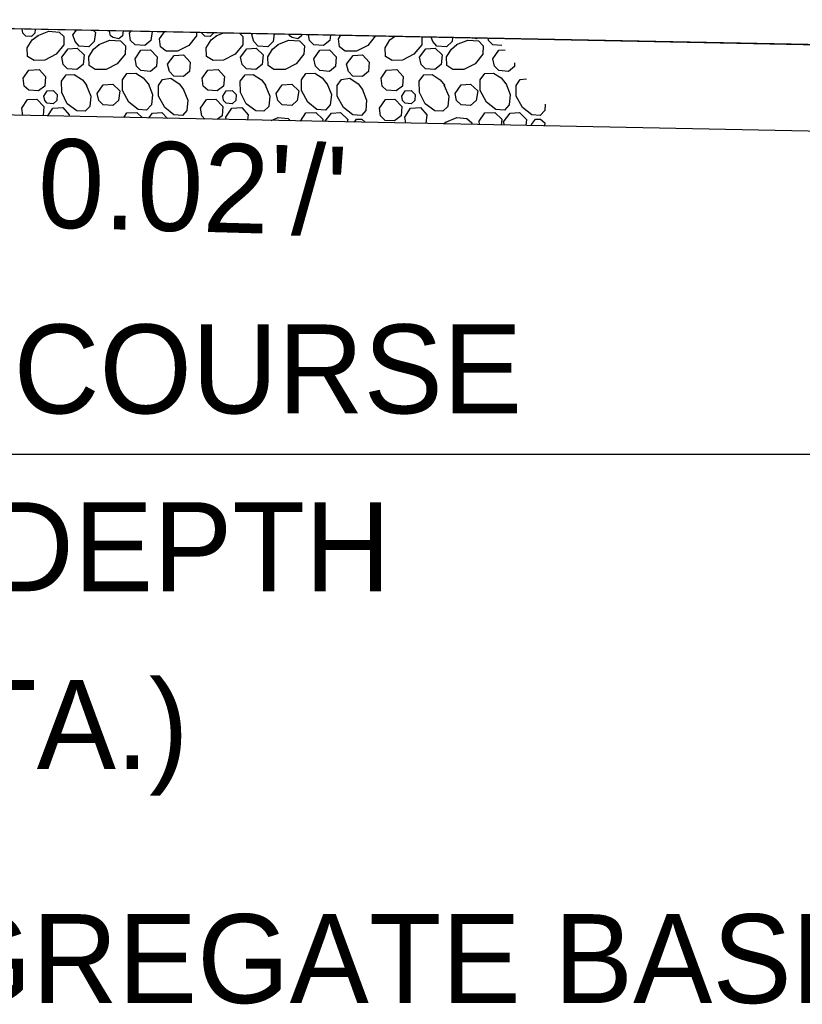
# Model space of a CAD drawing. Extents: x 2478 to 3210, y 439 to 841.
# Drawn here: x 2631.89 to 2642.46, y 475.8 to 489.09 of the extents above; entities that cross this region are included whole.
import ezdxf

# ---------------------------------------------------------------- set-up
doc = ezdxf.new("R2010")
doc.units = 0
for name, color, linetype in [('19', 7, 'Continuous'), ('R_Annotation', 7, 'Continuous'), ('R_Dimension', 7, 'Continuous')]:
    doc.layers.add(name, color=color, linetype=linetype)

msp = doc.modelspace()

# ---------------------------------------------------------------- linework, layer by layer
at = {"layer": '19'}
msp.add_lwpolyline([(2604.697, 489.114), (2604.445, 488.609), (2627.034, 489.061), (2649.623, 488.609), (2649.371, 489.114), (2627.034, 489.561)], close=True, dxfattribs=at)
at = {"layer": 'R_Annotation'}
for p, q in [((2649.623, 488.609), (2627.034, 489.061)), ((2666.487, 487.104), (2627.034, 487.893))]:
    msp.add_line(p, q, dxfattribs=at)
at = {"layer": 'R_Dimension'}
for p, q in [((2632.609, 488.881), (2632.658, 488.948)), ((2633.104, 488.931), (2633.11, 488.939)), ((2633.374, 488.906), (2633.391, 488.933)), ((2634.544, 488.871), (2634.642, 488.908)), ((2635.024, 488.881), (2635.038, 488.9)), ((2631.933, 487.795), (2631.919, 487.891)), ((2634.68, 487.74), (2634.674, 487.771)), ((2637.105, 487.692), (2637.089, 487.771)), ((2637.611, 487.682), (2637.649, 487.711)), ((2638.1, 487.672), (2638.094, 487.716)), ((2638.438, 487.665), (2638.424, 487.711)), ((2638.801, 487.658), (2638.799, 487.671)), ((2649.034, 483.219), (2605.034, 483.219))]:
    msp.add_line(p, q, dxfattribs=at)
for points in [[(2632.101, 488.959), (2632.094, 488.906), (2632.049, 488.861), (2631.974, 488.866), (2631.934, 488.906), (2631.924, 488.963)], [(2632.129, 488.871), (2632.284, 488.931), (2632.424, 488.921), (2632.489, 488.861), (2632.489, 488.746), (2632.384, 488.621), (2632.229, 488.541), (2632.089, 488.536), (2631.999, 488.591), (2631.994, 488.706), (2632.059, 488.816), (2632.139, 488.876)], [(2632.888, 488.943), (2632.914, 488.916), (2632.899, 488.791), (2632.824, 488.721), (2632.694, 488.731), (2632.639, 488.791), (2632.609, 488.881)], [(2633.287, 488.935), (2633.279, 488.871), (2633.229, 488.831), (2633.154, 488.846), (2633.119, 488.871), (2633.104, 488.931)], [(2633.679, 488.928), (2633.664, 488.806), (2633.579, 488.741), (2633.449, 488.746), (2633.389, 488.806), (2633.374, 488.906)], [(2634.279, 488.916), (2634.279, 488.871), (2634.174, 488.741), (2634.024, 488.661), (2633.869, 488.661), (2633.794, 488.721), (2633.779, 488.831), (2633.846, 488.924)], [(2634.51, 488.911), (2634.509, 488.906), (2634.464, 488.861), (2634.389, 488.866), (2634.349, 488.906), (2634.348, 488.914)], [(2634.857, 488.904), (2634.904, 488.861), (2634.904, 488.746), (2634.799, 488.621), (2634.644, 488.541), (2634.504, 488.536), (2634.414, 488.591), (2634.409, 488.706), (2634.474, 488.816), (2634.554, 488.876)], [(2635.326, 488.895), (2635.314, 488.791), (2635.239, 488.721), (2635.109, 488.731), (2635.054, 488.791), (2635.024, 488.881)], [(2635.696, 488.887), (2635.694, 488.871), (2635.644, 488.831), (2635.569, 488.846), (2635.534, 488.871), (2635.529, 488.891)], [(2636.088, 488.879), (2636.079, 488.806), (2635.994, 488.741), (2635.864, 488.746), (2635.804, 488.806), (2635.792, 488.885)], [(2636.691, 488.867), (2636.589, 488.741), (2636.439, 488.661), (2636.284, 488.661), (2636.209, 488.721), (2636.194, 488.831), (2636.227, 488.877)], [(2636.882, 488.864), (2636.879, 488.861), (2636.813, 488.865)], [(2637.319, 488.855), (2637.319, 488.746), (2637.214, 488.621), (2637.059, 488.541), (2636.919, 488.536), (2636.829, 488.591), (2636.824, 488.706), (2636.889, 488.816), (2636.951, 488.862)], [(2632.959, 488.751), (2633.109, 488.811), (2633.254, 488.801), (2633.319, 488.736), (2633.314, 488.621), (2633.209, 488.491), (2633.059, 488.416), (2632.909, 488.416), (2632.829, 488.471), (2632.824, 488.586), (2632.889, 488.691), (2632.964, 488.751)], [(2635.374, 488.751), (2635.524, 488.811), (2635.669, 488.801), (2635.734, 488.736), (2635.729, 488.621), (2635.624, 488.491), (2635.474, 488.416), (2635.324, 488.416), (2635.244, 488.471), (2635.239, 488.586), (2635.304, 488.691), (2635.379, 488.751)], [(2637.736, 488.846), (2637.729, 488.791), (2637.654, 488.721), (2637.524, 488.731), (2637.469, 488.791), (2637.448, 488.852)], [(2637.789, 488.751), (2637.939, 488.811), (2638.084, 488.801), (2638.149, 488.736), (2638.144, 488.621), (2638.039, 488.491), (2637.889, 488.416), (2637.739, 488.416), (2637.659, 488.471), (2637.654, 488.586), (2637.719, 488.691), (2637.794, 488.751)], [(2638.071, 488.84), (2638.059, 488.831), (2638.006, 488.841)], [(2638.398, 488.741), (2638.279, 488.746), (2638.219, 488.806), (2638.214, 488.837)], [(2632.459, 488.581), (2632.544, 488.696), (2632.669, 488.701), (2632.764, 488.611), (2632.749, 488.481), (2632.664, 488.416), (2632.539, 488.426), (2632.479, 488.481), (2632.459, 488.581)], [(2633.449, 488.561), (2633.529, 488.676), (2633.659, 488.681), (2633.749, 488.586), (2633.739, 488.456), (2633.659, 488.386), (2633.529, 488.401), (2633.469, 488.461), (2633.449, 488.561)], [(2633.889, 488.486), (2633.979, 488.606), (2634.104, 488.611), (2634.194, 488.516), (2634.184, 488.386), (2634.104, 488.321), (2633.974, 488.326), (2633.914, 488.386), (2633.889, 488.486)], [(2634.874, 488.581), (2634.959, 488.696), (2635.084, 488.701), (2635.179, 488.611), (2635.164, 488.481), (2635.079, 488.416), (2634.954, 488.426), (2634.894, 488.481), (2634.874, 488.581)], [(2635.864, 488.561), (2635.944, 488.676), (2636.074, 488.681), (2636.164, 488.586), (2636.154, 488.456), (2636.074, 488.386), (2635.944, 488.401), (2635.884, 488.461), (2635.864, 488.561)], [(2636.304, 488.486), (2636.394, 488.606), (2636.519, 488.611), (2636.609, 488.516), (2636.599, 488.386), (2636.519, 488.321), (2636.389, 488.326), (2636.329, 488.386), (2636.304, 488.486)], [(2637.289, 488.581), (2637.374, 488.696), (2637.499, 488.701), (2637.594, 488.611), (2637.579, 488.481), (2637.494, 488.416), (2637.369, 488.426), (2637.309, 488.481), (2637.289, 488.581)], [(2638.279, 488.561), (2638.359, 488.676), (2638.444, 488.679)], [(2638.573, 488.505), (2638.569, 488.456), (2638.489, 488.386), (2638.359, 488.401), (2638.299, 488.461), (2638.279, 488.561)], [(2631.939, 488.296), (2632.014, 488.406), (2632.154, 488.416), (2632.239, 488.321), (2632.229, 488.191), (2632.144, 488.126), (2632.014, 488.136), (2631.954, 488.191), (2631.939, 488.296)], [(2632.789, 488.206), (2632.854, 488.056), (2632.839, 487.916), (2632.774, 487.851), (2632.664, 487.856), (2632.534, 487.951), (2632.459, 488.106), (2632.454, 488.256), (2632.519, 488.341), (2632.629, 488.346), (2632.739, 488.276), (2632.799, 488.201)], [(2633.624, 488.231), (2633.684, 488.076), (2633.669, 487.936), (2633.604, 487.866), (2633.489, 487.876), (2633.364, 487.976), (2633.279, 488.131), (2633.279, 488.276), (2633.339, 488.361), (2633.459, 488.366), (2633.559, 488.301), (2633.624, 488.221)], [(2634.354, 488.296), (2634.429, 488.406), (2634.569, 488.416), (2634.654, 488.321), (2634.644, 488.191), (2634.559, 488.126), (2634.429, 488.136), (2634.369, 488.191), (2634.354, 488.296)], [(2635.204, 488.206), (2635.269, 488.056), (2635.254, 487.916), (2635.189, 487.851), (2635.079, 487.856), (2634.949, 487.951), (2634.874, 488.106), (2634.869, 488.256), (2634.934, 488.341), (2635.044, 488.346), (2635.154, 488.276), (2635.214, 488.201)], [(2636.039, 488.231), (2636.099, 488.076), (2636.084, 487.936), (2636.019, 487.866), (2635.904, 487.876), (2635.779, 487.976), (2635.694, 488.131), (2635.694, 488.276), (2635.754, 488.361), (2635.874, 488.366), (2635.974, 488.301), (2636.039, 488.221)], [(2636.769, 488.296), (2636.844, 488.406), (2636.984, 488.416), (2637.069, 488.321), (2637.059, 488.191), (2636.974, 488.126), (2636.844, 488.136), (2636.784, 488.191), (2636.769, 488.296)], [(2637.619, 488.206), (2637.684, 488.056), (2637.669, 487.916), (2637.604, 487.851), (2637.494, 487.856), (2637.364, 487.951), (2637.289, 488.106), (2637.284, 488.256), (2637.349, 488.341), (2637.459, 488.346), (2637.569, 488.276), (2637.629, 488.201)], [(2638.454, 488.231), (2638.514, 488.076), (2638.499, 487.936), (2638.434, 487.866), (2638.319, 487.876), (2638.194, 487.976), (2638.109, 488.131), (2638.109, 488.276), (2638.169, 488.361), (2638.289, 488.366), (2638.389, 488.301), (2638.454, 488.221)], [(2632.939, 488.091), (2633.019, 488.206), (2633.149, 488.216), (2633.244, 488.126), (2633.224, 487.996), (2633.149, 487.931), (2633.019, 487.936), (2632.959, 487.996), (2632.939, 488.091)], [(2634.099, 488.156), (2634.159, 488.001), (2634.149, 487.861), (2634.089, 487.796), (2633.974, 487.801), (2633.849, 487.901), (2633.764, 488.056), (2633.764, 488.201), (2633.819, 488.281), (2633.934, 488.296), (2634.044, 488.221), (2634.104, 488.146)], [(2635.354, 488.091), (2635.434, 488.206), (2635.564, 488.216), (2635.659, 488.126), (2635.639, 487.996), (2635.564, 487.931), (2635.434, 487.936), (2635.374, 487.996), (2635.354, 488.091)], [(2636.514, 488.156), (2636.574, 488.001), (2636.564, 487.861), (2636.504, 487.796), (2636.389, 487.801), (2636.264, 487.901), (2636.179, 488.056), (2636.179, 488.201), (2636.234, 488.281), (2636.349, 488.296), (2636.459, 488.221), (2636.519, 488.146)], [(2637.769, 488.091), (2637.849, 488.206), (2637.979, 488.216), (2638.074, 488.126), (2638.054, 487.996), (2637.979, 487.931), (2637.849, 487.936), (2637.789, 487.996), (2637.769, 488.091)], [(2638.985, 487.948), (2638.979, 487.861), (2638.919, 487.796), (2638.804, 487.801), (2638.679, 487.901), (2638.594, 488.056), (2638.594, 488.201), (2638.649, 488.281), (2638.731, 488.291)], [(2632.219, 488.056), (2632.264, 488.126), (2632.344, 488.131), (2632.399, 488.076), (2632.394, 487.996), (2632.344, 487.951), (2632.264, 487.961), (2632.229, 487.996), (2632.219, 488.056)], [(2634.634, 488.056), (2634.679, 488.126), (2634.759, 488.131), (2634.814, 488.076), (2634.809, 487.996), (2634.759, 487.951), (2634.679, 487.961), (2634.644, 487.996), (2634.634, 488.056)], [(2637.049, 488.056), (2637.094, 488.126), (2637.174, 488.131), (2637.229, 488.076), (2637.224, 487.996), (2637.174, 487.951), (2637.094, 487.961), (2637.059, 487.996), (2637.049, 488.056)], [(2631.919, 487.891), (2631.999, 488.011), (2632.124, 488.016), (2632.219, 487.916), (2632.209, 487.791), (2632.208, 487.79)], [(2634.334, 487.891), (2634.414, 488.011), (2634.539, 488.016), (2634.634, 487.916), (2634.624, 487.791), (2634.562, 487.743)], [(2636.749, 487.891), (2636.829, 488.011), (2636.954, 488.016), (2637.049, 487.916), (2637.039, 487.791), (2636.949, 487.721), (2636.824, 487.726), (2636.764, 487.791), (2636.749, 487.891)], [(2632.271, 487.789), (2632.339, 487.891), (2632.474, 487.901), (2632.559, 487.801), (2632.557, 487.783)], [(2633.298, 487.768), (2633.339, 487.831), (2633.474, 487.836), (2633.551, 487.763)], [(2633.634, 487.761), (2633.684, 487.826), (2633.809, 487.836), (2633.888, 487.756)], [(2634.39, 487.746), (2634.349, 487.791), (2634.334, 487.891)], [(2634.674, 487.771), (2634.754, 487.891), (2634.889, 487.901), (2634.974, 487.801), (2634.966, 487.735)], [(2635.682, 487.72), (2635.754, 487.831), (2635.889, 487.836), (2635.984, 487.746), (2635.98, 487.714)], [(2636.011, 487.714), (2636.099, 487.826), (2636.224, 487.836), (2636.319, 487.741), (2636.314, 487.708)], [(2637.089, 487.771), (2637.169, 487.891), (2637.304, 487.901), (2637.389, 487.801), (2637.376, 487.686)], [(2638.094, 487.716), (2638.169, 487.831), (2638.304, 487.836), (2638.399, 487.746), (2638.39, 487.666)], [(2638.424, 487.711), (2638.514, 487.826), (2638.639, 487.836), (2638.734, 487.741), (2638.722, 487.66)], [(2635.286, 487.728), (2635.379, 487.766), (2635.514, 487.756), (2635.549, 487.723)], [(2636.41, 487.706), (2636.439, 487.746), (2636.509, 487.746), (2636.556, 487.703)], [(2637.644, 487.706), (2637.794, 487.766), (2637.929, 487.756), (2637.994, 487.696), (2637.994, 487.674)], [(2638.799, 487.671), (2638.854, 487.746), (2638.924, 487.746), (2638.979, 487.696), (2638.977, 487.654)]]:
    msp.add_lwpolyline(points, dxfattribs=at)

# ---------------------------------------------------------------- texts
at = {"layer": 'R_Annotation'}
msp.add_text("0.02'/'", height=1.2, rotation=358.3978, dxfattribs=at).set_placement((2632.124, 486.287))
for s, p in [('22\'-0" AGGREGATE BASE COURSE', (2611.938, 483.774)), ('(CLASS 7) - 6" COMP\'D. DEPTH', (2613.289, 481.374)), ('(85.50 TONS PER STA.)', (2616.426, 478.974)), ('AGGREGATE BASE COURSE', (2628.491, 475.816))]:
    msp.add_text(s, height=1.2, dxfattribs=at).set_placement(p)

doc.saveas('drawing.dxf')
